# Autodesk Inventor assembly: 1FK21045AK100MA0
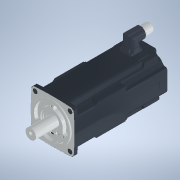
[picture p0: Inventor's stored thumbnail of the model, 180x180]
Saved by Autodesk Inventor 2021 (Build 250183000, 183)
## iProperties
Category: PARTsolutions
Created: 2026-06
Part Number: 1FK21045AK100MA0
Catalog Web Link: www.3dfindit.com
Description: 1FK21045AK100MA0-Servo synchronous motor
Document SubType Name: Assembly
Designer: psAdmin
Mass: 961.159 g
Surface Area: 1195.26 cm^2
Volume: 961.159 cm^3
Density: 1 g/cm^3
Title: 1FK21045AK100MA0
Author: Cadenas PARTsolutions
Comments: Servo synchronous motor
PSOL_IDENT_0: {$CADENAS_DATA/23d-libs/siemens_ag/_cat_/e0/5f/1fk21045ak100ma0.prj},193 {STYP=ASS},{VTYP=3D},{NB=1F
PSOL_IDENT_1: K21045AK100MA0},{LINA=1FK21045AK100MA0},{NN=1FK21045AK100MA0},{DATE=19.08.2025 14:01:03},{GEOMDATE=3
PSOL_IDENT_2: 0.07.2025 02:01:57},{VERSION=},{LINEID=10},{WBVAR=},{WBNUMERIC=}  {NB=1FK21045AK100MA0},{LINA=1FK210
PSOL_IDENT_3: 45AK100MA0},{KT=DUMMY},{PREVIEW=../../../_pool_/0f/2c/p_d211_xx_00438j.png},{DESCSHORT=SIMOTICS S-1F
PSOL_IDENT_4: K2 HD, SINAMICS S210 3AC 400V-480V, 1.7 Nm, 6000 rpm},{DESCLONG=SIMOTICS S-1FK2 HD servo motor M0=2.
PSOL_IDENT_5: 4 Nm; PN = 1.07 kW at nN=6000 rpm (380-480 V); PN = 0.75 kW at nN=3000 rpm (200-240 V); with holding
PSOL_IDENT_6: brake; degree of protection IP64; cylindrical shaft D19x40mm; absolute encoder 22-bit + 12-bit mult
PSOL_IDENT_7: iturn (encoder AM22DQC); with OCC interface; plug size M17, rotatable; SIMOTICS S-1FK2 servomotorfor
PSOL_IDENT_8: a wide range of uses in industrial environments. SIMOTICS S‑1FK2 servomotors are compact synchronou
PSOL_IDENT_9: s motors with a high dynamic performance that set themselves apart as a result of their high power d
PSOL_IDENT_10: ensity, degree of protection and overload capability. The motors are available in two variants: as H
PSOL_IDENT_11: igh Dynamic variant (highest dynamic performance as a result of the low intrinsic moment of inertia
PSOL_IDENT_12: for applications demanding a high dynamic performance with low moved masses) - and as Compact varian
PSOL_IDENT_13: t (precise and stable closed-loop control for medium up to large moved masses as a result of a mediu
PSOL_IDENT_14: m intrinsic moment of inertia). SIMOTICSS‑1FK2 servomotors fully exploit their strengths in a system
PSOL_IDENT_15: with the SINAMICSS210 frequency converter and simple connection using the one cable connection (OCC
PSOL_IDENT_16: ). Advantages include the short control and positioning times, fast and precise correction of distur
PSOL_IDENT_17: bing quantities as well as stable control with a high dynamic performance. The servo motors can be c
PSOL_IDENT_18: onfigured to address a wide range of requirements. For example with and without holding brake, IP64
PSOL_IDENT_19: or IP65 degree of protection, singleturn or multiturn absolute encoders - to name just a few. Furthe
PSOL_IDENT_20: r, the servomotors are available in different shaft heights extending from 20 to 100. A shaft sealin
PSOL_IDENT_21: g ring is available to achieve an IP65 degree of protection and for subsequent mounting at the motor
PSOL_IDENT_22: or as spare part. SIMOTICS - the optimum motor for each and every motion control application.},{INT
PSOL_IDENT_23: NO=804766807114},{SUPPLIERALTNO=1FK2104-5AK10-0MA0},{MANUID=1FK21045AK100MA0},{MANUNAME=Siemens},{MA
PSOL_IDENT_24: NUTYPEDESC=Synchronous motor 1FK2-HD 2,39 Nm},{AAU732=SIMOTICS},{AAO057=S-1FK2},{AAU734=SIMOTICS S-1
PSOL_IDENT_25: FK2 HD servo motor M0=2.4 Nm; PN = 1.07 kW at nN=6000 rpm (380-480 V); PN = 0.75 kW at nN=3000 rpm (
PSOL_IDENT_26: 200-240 V); with holding brake; degree of protection IP64; cylindrical shaft D19x40mm; absolute enco
PSOL_IDENT_27: der 22-bit + 12-bit multiturn (encoder AM22DQC); with OCC interface; plug size M17, rotatable;},{AAW
PSOL_IDENT_28: 338=Synchronous motor 1FK2-HD 2,39 Nm},{AAO742=SIMOTICS},{AAO663=4042948691236},{NOCUPEROU=1},{PRICE
PSOL_IDENT_29: QUANTITY=1},{QUANTITYMIN=1},{QUANTITYINT=1},{CTN=85015100},{COO=DE},{AAO676=1FK2104-5AK10-0MA0},{AAO
PSOL_IDENT_30: 677=Siemens AG},{ORDERUNIT=C62},{CONTENTUNIT=C62}
NB: 1FK21045AK100MA0
NN: 1FK21045AK100MA0
NT: Servo synchronous motor
NBSYN: $MANUID.
LINA: 1FK21045AK100MA0
CATALOG: SIEMENS
PREVIEW: ../../../_pool_/0f/2c/p_d211_xx_00438j.png
DESCSHORT: SIMOTICS S-1FK2 HD, SINAMICS S210 3AC 400V-480V, 1.7 Nm, 6000 rpm
DESCLONG: SIMOTICS S-1FK2 HD servo motor M0=2.4 Nm; PN = 1.07 kW at nN=6000 rpm (380-480 V); PN = 0.75 kW at nN=3000 rpm (200-240 V); with holding brake; degree of protec
INTNO: 804766807114
SUPPLIERALTNO: 1FK2104-5AK10-0MA0
MANUID: 1FK21045AK100MA0
MANUNAME: Siemens
MANUTYPEDESC: Synchronous motor 1FK2-HD 2,39 Nm
AAU732: SIMOTICS
AAO057: S-1FK2
AAU734: SIMOTICS S-1FK2 HD servo motor M0=2.4 Nm; PN = 1.07 kW at nN=6000 rpm (380-480 V); PN = 0.75 kW at nN=3000 rpm (200-240 V); with holding brake; degree of protec
AAW338: Synchronous motor 1FK2-HD 2,39 Nm
AAO742: SIMOTICS
AAO663: 4042948691236.0
NOCUPEROU: 1
PRICEQUANTITY: 1
QUANTITYMIN: 1
QUANTITYINT: 1
CTN: 85015100
COO: DE
ARTICLENO: 1FK21045AK100MA0
BOMINFO: 1FK21045AK100MA0
CREATOR: CADENAS GmbH
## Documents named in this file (24)
- e:\temp\worker_COMMON_20\temp\tmp_1756_12_AqNtQ\format_0\1FK21045AK100MA0.iam
- e:\temp\worker_COMMON_20\temp\tmp_1756_12_AqNtQ\format_0\1FK21045AK100MA0_PART1.ipt
- e:\temp\worker_COMMON_20\temp\tmp_1756_12_AqNtQ\format_0\1FK21045AK100MA0_PART2.ipt
- e:\temp\worker_COMMON_20\temp\tmp_1756_12_AqNtQ\format_0\1FK21045AK100MA0_PART3.ipt
- e:\temp\worker_COMMON_20\temp\tmp_1756_12_AqNtQ\format_0\1FK21045AK100MA0_PART4.ipt
- e:\temp\worker_COMMON_20\temp\tmp_1756_12_AqNtQ\format_0\1FK21045AK100MA0_PART5.ipt
- e:\temp\worker_COMMON_20\temp\tmp_1756_12_AqNtQ\format_0\1FK21045AK100MA0_PART6.ipt
- e:\temp\worker_COMMON_20\temp\tmp_1756_12_AqNtQ\format_0\1FK21045AK100MA0_PART7.ipt
- e:\temp\worker_COMMON_20\temp\tmp_1756_12_AqNtQ\format_0\1FK21045AK100MA0_PART8.ipt
- e:\temp\worker_COMMON_20\temp\tmp_1756_12_AqNtQ\format_0\1FK21045AK100MA0_PART9.ipt
- e:\temp\worker_COMMON_20\temp\tmp_1756_12_AqNtQ\format_0\1FK21045AK100MA0_PART10.ipt
- e:\temp\worker_COMMON_20\temp\tmp_1756_12_AqNtQ\format_0\1FK21045AK100MA0_PART11.ipt
- e:\temp\worker_COMMON_20\temp\tmp_1756_12_AqNtQ\format_0\1FK21045AK100MA0_PART12.ipt
- e:\temp\worker_COMMON_20\temp\tmp_1756_12_AqNtQ\format_0\1FK21045AK100MA0_PART13.ipt
- e:\temp\worker_COMMON_20\temp\tmp_1756_12_AqNtQ\format_0\1FK21045AK100MA0_PART14.ipt
- e:\temp\worker_COMMON_20\temp\tmp_1756_12_AqNtQ\format_0\1FK21045AK100MA0_PART15.ipt
- e:\temp\worker_COMMON_20\temp\tmp_1756_12_AqNtQ\format_0\1FK21045AK100MA0_PART16.ipt
- e:\temp\worker_COMMON_20\temp\tmp_1756_12_AqNtQ\format_0\1FK21045AK100MA0_PART17.ipt
- e:\temp\worker_COMMON_20\temp\tmp_1756_12_AqNtQ\format_0\1FK21045AK100MA0_PART18.ipt
- e:\temp\worker_COMMON_20\temp\tmp_1756_12_AqNtQ\format_0\1FK21045AK100MA0_PART19.ipt
- e:\temp\worker_COMMON_20\temp\tmp_1756_12_AqNtQ\format_0\1FK21045AK100MA0_PART20.ipt
- e:\temp\worker_COMMON_20\temp\tmp_1756_12_AqNtQ\format_0\1FK21045AK100MA0_PART21.ipt
- e:\temp\worker_COMMON_20\temp\tmp_1756_12_AqNtQ\format_0\1FK21045AK100MA0_PART22.ipt
- e:\temp\worker_COMMON_20\temp\tmp_1756_12_AqNtQ\format_0\1FK21045AK100MA0_PART23.ipt
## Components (23 placed, 23 different names)
1. 1FK21045AK100MA0_PART1:1
2. 1FK21045AK100MA0_PART2:1
3. 1FK21045AK100MA0_PART3:1
4. 1FK21045AK100MA0_PART4:1
5. 1FK21045AK100MA0_PART5:1
6. 1FK21045AK100MA0_PART6:1
7. 1FK21045AK100MA0_PART7:1
8. 1FK21045AK100MA0_PART8:1
9. 1FK21045AK100MA0_PART9:1
10. 1FK21045AK100MA0_PART10:1
11. 1FK21045AK100MA0_PART11:1
12. 1FK21045AK100MA0_PART12:1
13. 1FK21045AK100MA0_PART13:1
14. 1FK21045AK100MA0_PART14:1
15. 1FK21045AK100MA0_PART15:1
16. 1FK21045AK100MA0_PART16:1
17. 1FK21045AK100MA0_PART17:1
18. 1FK21045AK100MA0_PART18:1
19. 1FK21045AK100MA0_PART19:1
20. 1FK21045AK100MA0_PART20:1
21. 1FK21045AK100MA0_PART21:1
22. 1FK21045AK100MA0_PART22:1
23. 1FK21045AK100MA0_PART23:1
